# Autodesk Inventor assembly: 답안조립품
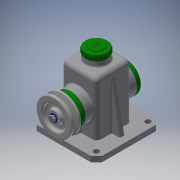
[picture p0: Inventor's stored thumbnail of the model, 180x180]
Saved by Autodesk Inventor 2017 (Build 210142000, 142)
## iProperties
Part Number: 답안조립품
Material: 일반
Document SubType Name: Assembly
Designer: 20
Author: 20
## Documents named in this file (14)
- C:\Users\20\Desktop\470818V1002\답안조립품.iam
- C:\Users\20\Desktop\470818V1002\본체.ipt
- C:\Users\20\Desktop\470818V1002\앞커버.ipt
- C:\Users\20\Desktop\470818V1002\뒤커버.ipt
- C:\Users\20\Desktop\470818V1002\베어링 15 x 35 x 11.ipt
- C:\Users\20\Desktop\470818V1002\축.ipt
- C:\Users\20\Desktop\470818V1002\멈춤링 15 x 1.ipt
- C:\Users\20\Desktop\470818V1002\오일실 15 25 7.ipt
- C:\Users\20\Desktop\470818V1002\키 5 x 5 x 14.ipt
- C:\Users\20\Desktop\470818V1002\V-벨트풀리.ipt
- C:\Users\20\Desktop\470818V1002\와셔.ipt
- C:\Users\20\Desktop\470818V1002\볼트 M6 x 12.ipt
- C:\Users\20\Desktop\470818V1002\볼트 M4 x 10.ipt
- C:\Users\20\Desktop\470818V1002\상부캡.ipt
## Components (1 placed, 1 different names)
1. V-벨트풀리:1 — 플러쉬:1
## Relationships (1: Flush 1)
- 플러쉬:1 [Flush]: V-벨트풀리:1
